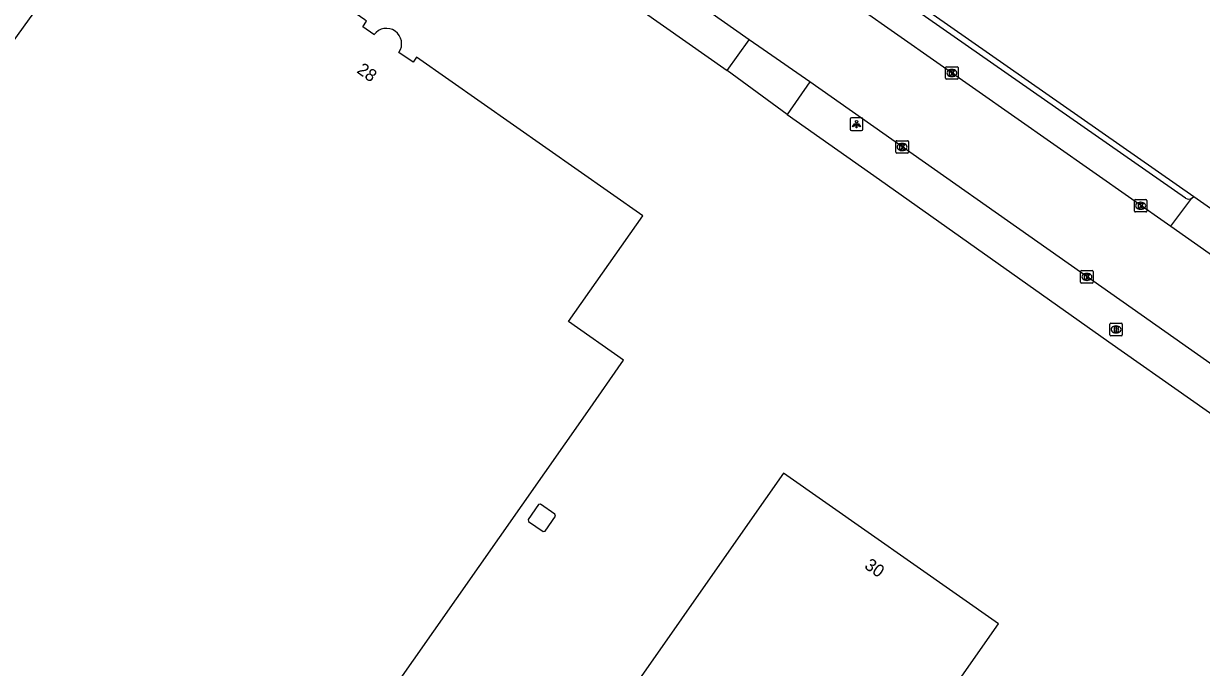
# Model space of a CAD drawing. Extents: x 155018 to 156648, y 383980 to 385733.
# Drawn here: x 155513.9 to 155608.1, y 384875.8 to 384927.2 of the extents above; entities that cross this region are included whole.
import ezdxf

# ---------------------------------------------------------------- set-up
doc = ezdxf.new("R2010")
doc.units = 0
for name, color, linetype in [('IMGEO_Brandkraan', 7, 'Continuous'), ('IMGEO_Kolk', 7, 'Continuous'), ('IMGEO_Lage_trafo', 7, 'Continuous'), ('IMGEO_Lichtpunt', 7, 'Continuous'), ('IMGEO_Pand', 7, 'Continuous'), ('IMGEO_Pand_nummerreeks', 7, 'Continuous'), ('IMGEO_Parkeervlak_open', 7, 'Continuous'), ('IMGEO_Rijbaan_lokaal_gesloten', 7, 'Continuous'), ('IMGEO_Voetpad_open', 7, 'Continuous')]:
    doc.layers.add(name, color=color, linetype=linetype)

msp = doc.modelspace()

# ---------------------------------------------------------------- linework, layer by layer
at = {"layer": 'IMGEO_Brandkraan'}
for p, q in [((155600.733, 384902.367), (155600.733, 384903.219)), ((155600.808, 384903.293), (155601.66, 384903.293)), ((155601.221, 384903.073), (155601.246, 384903.073)), ((155601.734, 384903.219), (155601.734, 384902.367)), ((155601.66, 384902.293), (155600.808, 384902.293)), ((155601.244, 384902.513), (155601.219, 384902.513))]:
    msp.add_line(p, q, dxfattribs=at)
for points in [[(155600.733, 384902.367), (155600.733, 384903.219)], [(155600.808, 384903.293), (155601.66, 384903.293)], [(155601.081, 384902.993), (155601.081, 384902.593), (155601.294, 384902.593)], [(155601.312, 384902.993), (155601.081, 384902.993)], [(155601.26, 384902.912), (155601.206, 384902.912), (155601.206, 384902.836)], [(155601.206, 384902.836), (155601.259, 384902.836)], [(155601.268, 384902.76), (155601.206, 384902.76), (155601.206, 384902.679)], [(155601.206, 384902.679), (155601.268, 384902.679)], [(155601.734, 384903.219), (155601.734, 384902.367)], [(155601.66, 384902.293), (155600.808, 384902.293)]]:
    msp.add_lwpolyline(points, dxfattribs=at)
for centre, radius, start, end in [((155600.81, 384903.217), 0.0765, 91.55205, 178.44795), ((155600.81, 384903.217), 0.0765, 91.55205, 178.44795), ((155601.261, 384902.874), 0.0379, 267.82845, 90.93552), ((155601.269, 384902.719), 0.0404, 269.87594, 90.50774), ((155601.3, 384902.844), 0.251, 268.66757, 293.53466), ((155601.316, 384902.848), 0.145, 59.4692, 91.53667), ((155601.341, 384902.895), 0.0922, 285.51372, 58.15012), ((155601.346, 384902.703), 0.105, 301.31148, 78.98903), ((155601.658, 384903.217), 0.0765, 1.55205, 88.44795), ((155601.658, 384903.217), 0.0765, 1.55205, 88.44795), ((155600.81, 384902.369), 0.0765, 181.55205, 268.44795), ((155600.81, 384902.369), 0.0765, 181.55205, 268.44795), ((155601.658, 384902.369), 0.0765, 271.55205, 358.44795), ((155601.658, 384902.369), 0.0765, 271.55205, 358.44795)]:
    msp.add_arc(centre, radius, start, end, dxfattribs=at)
for centre, major_axis, ratio, start_param, end_param in [((155601.22, 384902.793), (-0.387, 0.002), 0.722429, 4.712389, 7.853982), ((155601.245, 384902.793), (-0.39, 0.002), 0.717154, 1.570796, 4.712389)]:
    msp.add_ellipse(centre, major_axis=major_axis, ratio=ratio, start_param=start_param, end_param=end_param, dxfattribs=at)
at = {"layer": 'IMGEO_Kolk'}
for p, q in [((155587.6, 384922.861), (155587.6, 384923.713)), ((155587.675, 384923.787), (155588.527, 384923.787)), ((155588.088, 384923.567), (155588.113, 384923.567)), ((155588.601, 384923.713), (155588.601, 384922.861)), ((155588.527, 384922.787), (155587.675, 384922.787)), ((155588.111, 384923.007), (155588.086, 384923.007)), ((155583.621, 384916.948), (155583.621, 384917.8)), ((155583.696, 384917.874), (155584.548, 384917.874)), ((155584.109, 384917.654), (155584.134, 384917.654)), ((155584.622, 384917.8), (155584.622, 384916.948)), ((155584.548, 384916.874), (155583.696, 384916.874)), ((155584.132, 384917.094), (155584.107, 384917.094)), ((155602.702, 384912.253), (155602.702, 384913.105)), ((155602.777, 384913.179), (155603.629, 384913.179)), ((155603.19, 384912.959), (155603.215, 384912.959)), ((155603.703, 384913.105), (155603.703, 384912.253)), ((155603.629, 384912.179), (155602.777, 384912.179)), ((155603.213, 384912.399), (155603.188, 384912.399)), ((155598.401, 384906.57), (155598.401, 384907.422)), ((155598.476, 384907.496), (155599.328, 384907.496)), ((155598.889, 384907.276), (155598.914, 384907.276)), ((155599.402, 384907.422), (155599.402, 384906.57)), ((155599.328, 384906.496), (155598.476, 384906.496)), ((155598.912, 384906.716), (155598.887, 384906.716))]:
    msp.add_line(p, q, dxfattribs=at)
for points in [[(155587.6, 384922.861), (155587.6, 384923.713)], [(155587.675, 384923.787), (155588.527, 384923.787)], [(155587.921, 384923.487), (155588.044, 384923.487), (155588.044, 384923.336), (155588.174, 384923.487), (155588.338, 384923.487), (155588.192, 384923.336), (155588.345, 384923.087), (155588.193, 384923.087), (155588.108, 384923.251), (155588.044, 384923.184), (155588.044, 384923.087), (155587.921, 384923.087), (155587.921, 384923.487)], [(155588.601, 384923.713), (155588.601, 384922.861)], [(155588.527, 384922.787), (155587.675, 384922.787)], [(155583.621, 384916.948), (155583.621, 384917.8)], [(155583.696, 384917.874), (155584.548, 384917.874)], [(155584.622, 384917.8), (155584.622, 384916.948)], [(155584.548, 384916.874), (155583.696, 384916.874)], [(155583.942, 384917.574), (155584.065, 384917.574), (155584.065, 384917.423), (155584.195, 384917.574), (155584.359, 384917.574), (155584.213, 384917.423), (155584.366, 384917.174), (155584.214, 384917.174), (155584.129, 384917.338), (155584.065, 384917.271), (155584.065, 384917.174), (155583.942, 384917.174), (155583.942, 384917.574)], [(155602.702, 384912.253), (155602.702, 384913.105)], [(155602.777, 384913.179), (155603.629, 384913.179)], [(155603.703, 384913.105), (155603.703, 384912.253)], [(155603.629, 384912.179), (155602.777, 384912.179)], [(155603.023, 384912.879), (155603.146, 384912.879), (155603.146, 384912.728), (155603.276, 384912.879), (155603.44, 384912.879), (155603.294, 384912.728), (155603.447, 384912.479), (155603.295, 384912.479), (155603.21, 384912.643), (155603.146, 384912.576), (155603.146, 384912.479), (155603.023, 384912.479), (155603.023, 384912.879)], [(155598.401, 384906.57), (155598.401, 384907.422)], [(155598.476, 384907.496), (155599.328, 384907.496)], [(155599.402, 384907.422), (155599.402, 384906.57)], [(155599.328, 384906.496), (155598.476, 384906.496)], [(155598.722, 384907.196), (155598.845, 384907.196), (155598.845, 384907.045), (155598.975, 384907.196), (155599.139, 384907.196), (155598.993, 384907.045), (155599.146, 384906.796), (155598.994, 384906.796), (155598.909, 384906.96), (155598.845, 384906.893), (155598.845, 384906.796), (155598.722, 384906.796), (155598.722, 384907.196)]]:
    msp.add_lwpolyline(points, dxfattribs=at)
for centre, start, end in [((155587.677, 384923.711), 91.55205, 178.44795), ((155587.677, 384923.711), 91.55205, 178.44795), ((155588.525, 384923.711), 1.55205, 88.44795), ((155588.525, 384923.711), 1.55205, 88.44795), ((155587.677, 384922.863), 181.55205, 268.44795), ((155587.677, 384922.863), 181.55205, 268.44795), ((155588.525, 384922.863), 271.55205, 358.44795), ((155588.525, 384922.863), 271.55205, 358.44795), ((155583.698, 384917.798), 91.55205, 178.44795), ((155583.698, 384917.798), 91.55205, 178.44795), ((155584.546, 384917.798), 1.55205, 88.44795), ((155584.546, 384917.798), 1.55205, 88.44795), ((155583.698, 384916.95), 181.55205, 268.44795), ((155583.698, 384916.95), 181.55205, 268.44795), ((155584.546, 384916.95), 271.55205, 358.44795), ((155584.546, 384916.95), 271.55205, 358.44795), ((155602.779, 384913.103), 91.55205, 178.44795), ((155602.779, 384913.103), 91.55205, 178.44795), ((155603.627, 384913.103), 1.55205, 88.44795), ((155603.627, 384913.103), 1.55205, 88.44795), ((155602.779, 384912.255), 181.55205, 268.44795), ((155602.779, 384912.255), 181.55205, 268.44795), ((155603.627, 384912.255), 271.55205, 358.44795), ((155603.627, 384912.255), 271.55205, 358.44795), ((155598.478, 384907.42), 91.55205, 178.44795), ((155598.478, 384907.42), 91.55205, 178.44795), ((155599.326, 384907.42), 1.55205, 88.44795), ((155599.326, 384907.42), 1.55205, 88.44795), ((155598.478, 384906.572), 181.55205, 268.44795), ((155598.478, 384906.572), 181.55205, 268.44795), ((155599.326, 384906.572), 271.55205, 358.44795), ((155599.326, 384906.572), 271.55205, 358.44795)]:
    msp.add_arc(centre, 0.0765, start, end, dxfattribs=at)
for centre, major_axis, ratio, start_param, end_param in [((155588.087, 384923.287), (-0.387, 0.002), 0.722429, 4.712389, 7.853982), ((155588.112, 384923.287), (-0.39, 0.002), 0.717154, 1.570796, 4.712389), ((155584.108, 384917.374), (-0.387, 0.002), 0.722429, 4.712389, 7.853982), ((155584.133, 384917.374), (-0.39, 0.002), 0.717154, 1.570796, 4.712389), ((155603.189, 384912.679), (-0.387, 0.002), 0.722429, 4.712389, 7.853982), ((155603.214, 384912.679), (-0.39, 0.002), 0.717154, 1.570796, 4.712389), ((155598.888, 384906.996), (-0.387, 0.002), 0.722429, 4.712389, 7.853982), ((155598.913, 384906.996), (-0.39, 0.002), 0.717154, 1.570796, 4.712389)]:
    msp.add_ellipse(centre, major_axis=major_axis, ratio=ratio, start_param=start_param, end_param=end_param, dxfattribs=at)
at = {"layer": 'IMGEO_Lage_trafo'}
msp.add_lwpolyline([(155555.406, 384886.647), (155555.573, 384886.675), (155556.385, 384887.869), (155556.356, 384888.035), (155555.196, 384888.823), (155555.029, 384888.799), (155554.209, 384887.598), (155554.251, 384887.44), (155555.406, 384886.647)], dxfattribs=at)
at = {"layer": 'IMGEO_Lichtpunt'}
for p, q in [((155579.979, 384919.599), (155579.979, 384918.792)), ((155579.979, 384919.599), (155579.979, 384918.792)), ((155580.881, 384919.694), (155580.073, 384919.694)), ((155580.881, 384919.694), (155580.073, 384919.694)), ((155580.975, 384918.792), (155580.975, 384919.599)), ((155580.975, 384918.792), (155580.975, 384919.599)), ((155580.073, 384918.698), (155580.881, 384918.698)), ((155580.073, 384918.698), (155580.881, 384918.698))]:
    msp.add_line(p, q, dxfattribs=at)
for points in [[(155580.353, 384919.263), (155580.392, 384919.235), (155580.204, 384918.973), (155580.166, 384919), (155580.353, 384919.263)], [(155580.455, 384919.215), (155580.502, 384919.215), (155580.502, 384918.893), (155580.455, 384918.893), (155580.455, 384919.215)], [(155580.565, 384919.235), (155580.603, 384919.262), (155580.79, 384919), (155580.751, 384918.972), (155580.565, 384919.235)]]:
    msp.add_lwpolyline(points, dxfattribs=at)
msp.add_circle((155580.478, 384919.397), 0.0994, dxfattribs=at)
for centre, start, end in [((155580.073, 384919.599), 90, 180), ((155580.073, 384919.599), 90, 180), ((155580.881, 384919.599), 0, 90), ((155580.881, 384919.599), 0, 90), ((155580.073, 384918.792), 180, 270), ((155580.073, 384918.792), 180, 270), ((155580.881, 384918.792), 270, 0), ((155580.881, 384918.792), 270, 360)]:
    msp.add_arc(centre, 0.0946, start, end, dxfattribs=at)
at = {"layer": 'IMGEO_Pand'}
for points in [[(155541.878, 384926.35), (155540.987, 384926.985), (155541.289, 384927.418), (155541.136, 384927.524), (155527.474, 384937.038), (155521.497, 384928.598), (155517.232, 384931.679), (155514.306, 384927.626), (155500, 384907.81), (155485.234, 384887.357), (155500, 384877.008), (155507.887, 384871.48), (155530.489, 384855.639), (155531.075, 384856.475), (155538.96, 384850.949)], [(155540.579, 384853.259), (155532.714, 384858.794), (155558.976, 384896.238), (155561.847, 384900.331), (155557.442, 384903.43), (155563.372, 384911.879), (155545.287, 384924.561), (155545.004, 384924.158), (155543.877, 384924.937)], [(155538.96, 384850.949), (155543.923, 384847.471), (155543.355, 384846.66), (155560.52, 384834.638), (155560.868, 384835.103), (155575.198, 384855.542), (155591.828, 384879.262), (155574.63, 384891.294), (155571.761, 384887.2), (155545.535, 384849.771), (155540.579, 384853.259)]]:
    msp.add_lwpolyline(points, dxfattribs=at)
msp.add_arc((155542.869, 384925.631), 1.224, 325.45149, 144.03909, dxfattribs=at)
at = {"layer": 'IMGEO_Parkeervlak_open'}
for points in [[(155605.603, 384911.034), (155607.302, 384913.282)], [(155607.46, 384913.427), (155617.317, 384906.512)]]:
    msp.add_lwpolyline(points, dxfattribs=at)
at = {"layer": 'IMGEO_Rijbaan_lokaal_gesloten'}
for points in [[(155571.894, 384925.942), (155541.6, 384947.23), (155536.91, 384950.526)], [(155580.666, 384928.528), (155605.603, 384911.034)], [(155576.741, 384922.577), (155573.015, 384925.172), (155571.894, 384925.942)], [(155647.55, 384872.837), (155615.591, 384895.277), (155602.522, 384904.454), (155576.741, 384922.577)], [(155605.603, 384911.034), (155615.524, 384904.073)]]:
    msp.add_lwpolyline(points, dxfattribs=at)
at = {"layer": 'IMGEO_Voetpad_open'}
for points in [[(155535.161, 384948.038), (155539.854, 384944.743), (155570.133, 384923.483)], [(155560.229, 384946.497), (155580.857, 384931.994), (155586.597, 384927.958), (155607.46, 384913.427)], [(155606.786, 384913.278), (155586.27, 384927.599), (155582.038, 384930.579)], [(155570.133, 384923.483), (155571.894, 384925.942)], [(155574.917, 384919.981), (155570.133, 384923.483)], [(155576.741, 384922.577), (155574.917, 384919.981)], [(155574.917, 384919.981), (155582.308, 384914.778), (155600.657, 384901.793), (155613.715, 384892.628), (155645.703, 384870.176)], [(155607.302, 384913.282), (155607.46, 384913.427)]]:
    msp.add_lwpolyline(points, dxfattribs=at)
msp.add_arc((155607.041, 384913.728), 0.517, 240.49681, 300.39148, dxfattribs=at)

# ---------------------------------------------------------------- texts
at = {"layer": 'IMGEO_Pand_nummerreeks'}
for s, rotation, p in [('28', 324.86369, (155540.437, 384923.361)), ('30', 325.02093, (155581.037, 384883.76))]:
    msp.add_text(s, height=1, rotation=rotation, dxfattribs=at).set_placement(p)

doc.saveas('drawing.dxf')
